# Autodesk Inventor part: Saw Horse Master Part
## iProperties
Created: 2010-08
Part Number: Saw Horse Master Part
Material: Default
Document SubType Name: Modeling
Designer: Paul Munford
Density: 1 g/cm^3
PlateThick: 12 mm
PlateLength: 120 mm
LegThick: 44 mm
LegWidth: 69 mm
TopThick: 44 mm
TopWidth: 94 mm
OALength: 700 mm
OAHeight: 532 mm
Author: Paul Munford
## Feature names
1. Top Board Ext [Extrusion]
2. Housing Loft
3. Housing Mirror [Mirror]
4. Housings Mirror [Mirror]
5. Leg Ext [Extrusion]
6. End Plate Ext [Extrusion]
7. End Plate Mirror [Mirror]
